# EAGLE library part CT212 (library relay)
ULTRA SMALL AUTOMOTIVE RELAY NAiS Twin type (8 terminals) en_ds_61205_0000.pdf
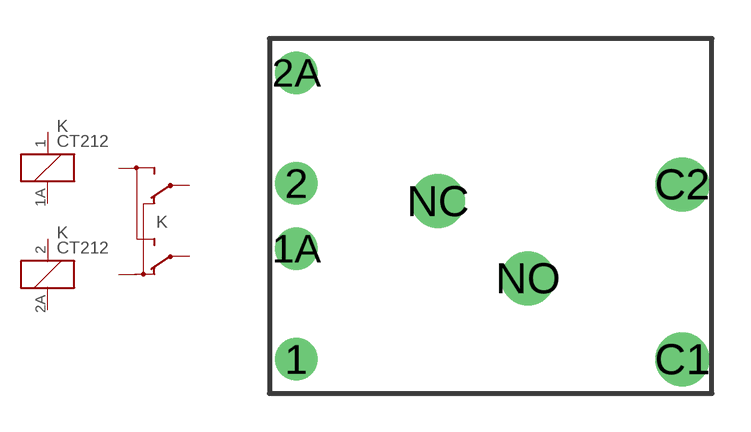
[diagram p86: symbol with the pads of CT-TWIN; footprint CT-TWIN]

Designator prefix K; gates A=K B=K 1=CF

## CT212 (OC_FARNELL: unknown; OC_NEWARK: unknown)  [CT-TWIN]
1  A:1  pas
1A  A:2  pas
2  B:1  pas
2A  B:2  pas
C1  1:COM1  pas
C2  1:COM2  pas
NC  1:NC  pas
NO  1:NO  pas

## Footprint CT-TWIN (pad centres in mm)
ULTRA SMALL AUTOMOTIVE RELAY NAiS Twin type (8 terminals) Source: http://www.mew-europe.com/.. en_ds_61205_0000.pdf
drill 1.1 round: 1 -7.45,-5.57; 1A -7.45,-1.27; 2 -7.45,1.27; 2A -7.45,5.57
drill 1.4 round: C1 7.55,-5.57; C2 7.55,1.23; NC -1.95,0.58; NO 1.55,-2.42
